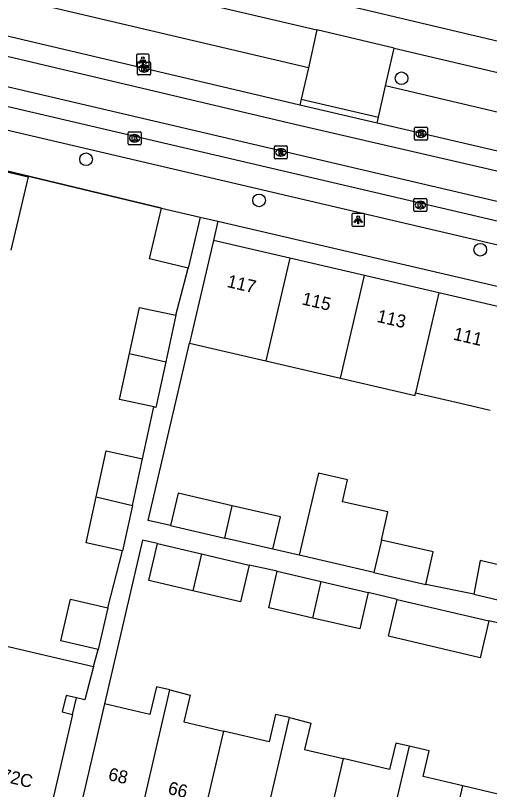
# Model space of a CAD drawing. Extents: x 163686 to 164493, y 382719 to 383870.
# Drawn here: x 163838.9 to 163875.6, y 383368 to 383427.9 of the extents above; entities that cross this region are included whole.
import ezdxf

# ---------------------------------------------------------------- set-up
doc = ezdxf.new("R2010")
doc.units = 0
for name, color, linetype in [('IMGEO_Boom', 7, 'Continuous'), ('IMGEO_Groenvoorziening', 7, 'Continuous'), ('IMGEO_Kolk', 7, 'Continuous'), ('IMGEO_Lichtpunt', 7, 'Continuous'), ('IMGEO_Muur', 7, 'Continuous'), ('IMGEO_Pand', 7, 'Continuous'), ('IMGEO_Pand_nummerreeks', 7, 'Continuous'), ('IMGEO_Rijbaan_lokaal_open', 7, 'Continuous'), ('IMGEO_Rioolput', 7, 'Continuous'), ('IMGEO_Voetpad_open', 7, 'Continuous')]:
    doc.layers.add(name, color=color, linetype=linetype)

msp = doc.modelspace()

# ---------------------------------------------------------------- linework, layer by layer
at = {"layer": 'IMGEO_Boom'}
for centre in [(163868.779, 383423.003), (163844.366, 383416.735), (163857.755, 383413.552), (163874.871, 383409.739)]:
    msp.add_circle(centre, 0.489, dxfattribs=at)
at = {"layer": 'IMGEO_Groenvoorziening'}
for points in [[(163861.569, 383423.819), (163837.373, 383429.512)], [(163890.603, 383416.989), (163867.54, 383422.415)]]:
    msp.add_lwpolyline(points, dxfattribs=at)
at = {"layer": 'IMGEO_Kolk'}
for p, q in [((163848.355, 383423.333), (163848.355, 383424.185)), ((163848.43, 383424.259), (163849.282, 383424.259)), ((163848.843, 383424.039), (163848.868, 383424.039)), ((163849.356, 383424.185), (163849.356, 383423.333)), ((163848.866, 383423.479), (163848.841, 383423.479)), ((163849.282, 383423.259), (163848.43, 383423.259)), ((163869.862, 383419.213), (163870.714, 383419.213)), ((163847.624, 383417.937), (163847.624, 383418.789)), ((163847.699, 383418.863), (163848.551, 383418.863)), ((163848.112, 383418.643), (163848.137, 383418.643)), ((163848.625, 383418.789), (163848.625, 383417.937)), ((163869.787, 383418.287), (163869.787, 383419.139)), ((163870.275, 383418.993), (163870.3, 383418.993)), ((163870.788, 383419.139), (163870.788, 383418.287)), ((163848.135, 383418.083), (163848.11, 383418.083)), ((163870.714, 383418.213), (163869.862, 383418.213)), ((163870.298, 383418.433), (163870.273, 383418.433)), ((163848.551, 383417.863), (163847.699, 383417.863)), ((163869.744, 383412.767), (163869.744, 383413.619)), ((163869.819, 383413.693), (163870.671, 383413.693)), ((163870.232, 383413.473), (163870.257, 383413.473)), ((163870.745, 383413.619), (163870.745, 383412.767)), ((163870.671, 383412.693), (163869.819, 383412.693)), ((163870.255, 383412.913), (163870.23, 383412.913))]:
    msp.add_line(p, q, dxfattribs=at)
for points in [[(163848.355, 383423.333), (163848.355, 383424.185)], [(163848.43, 383424.259), (163849.282, 383424.259)], [(163849.356, 383424.185), (163849.356, 383423.333)], [(163848.676, 383423.959), (163848.799, 383423.959), (163848.799, 383423.808), (163848.929, 383423.959), (163849.093, 383423.959), (163848.947, 383423.808), (163849.1, 383423.559), (163848.948, 383423.559), (163848.863, 383423.723), (163848.799, 383423.656), (163848.799, 383423.559), (163848.676, 383423.559), (163848.676, 383423.959)], [(163849.282, 383423.259), (163848.43, 383423.259)], [(163869.862, 383419.213), (163870.714, 383419.213)], [(163847.624, 383417.937), (163847.624, 383418.789)], [(163847.699, 383418.863), (163848.551, 383418.863)], [(163848.625, 383418.789), (163848.625, 383417.937)], [(163869.787, 383418.287), (163869.787, 383419.139)], [(163870.108, 383418.913), (163870.231, 383418.913), (163870.231, 383418.762), (163870.361, 383418.913), (163870.525, 383418.913), (163870.379, 383418.762), (163870.532, 383418.513), (163870.38, 383418.513), (163870.295, 383418.677), (163870.231, 383418.61), (163870.231, 383418.513), (163870.108, 383418.513), (163870.108, 383418.913)], [(163870.788, 383419.139), (163870.788, 383418.287)], [(163847.945, 383418.563), (163848.068, 383418.563), (163848.068, 383418.412), (163848.198, 383418.563), (163848.362, 383418.563), (163848.216, 383418.412), (163848.369, 383418.163), (163848.217, 383418.163), (163848.132, 383418.327), (163848.068, 383418.26), (163848.068, 383418.163), (163847.945, 383418.163), (163847.945, 383418.563)], [(163870.714, 383418.213), (163869.862, 383418.213)], [(163848.551, 383417.863), (163847.699, 383417.863)], [(163869.744, 383412.767), (163869.744, 383413.619)], [(163869.819, 383413.693), (163870.671, 383413.693)], [(163870.065, 383413.393), (163870.188, 383413.393), (163870.188, 383413.242), (163870.318, 383413.393), (163870.482, 383413.393), (163870.336, 383413.242), (163870.489, 383412.993), (163870.337, 383412.993), (163870.252, 383413.157), (163870.188, 383413.09), (163870.188, 383412.993), (163870.065, 383412.993), (163870.065, 383413.393)], [(163870.745, 383413.619), (163870.745, 383412.767)], [(163870.671, 383412.693), (163869.819, 383412.693)]]:
    msp.add_lwpolyline(points, dxfattribs=at)
for centre, start, end in [((163848.432, 383424.183), 91.55205, 178.44795), ((163848.432, 383424.183), 91.55205, 178.44795), ((163849.28, 383424.183), 1.55205, 88.44795), ((163849.28, 383424.183), 1.55205, 88.44795), ((163848.432, 383423.335), 181.55205, 268.44795), ((163848.432, 383423.335), 181.55205, 268.44795), ((163849.28, 383423.335), 271.55205, 358.44795), ((163849.28, 383423.335), 271.55205, 358.44795), ((163869.864, 383419.137), 91.55205, 178.44795), ((163869.864, 383419.137), 91.55205, 178.44795), ((163870.712, 383419.137), 1.55205, 88.44795), ((163870.712, 383419.137), 1.55205, 88.44795), ((163847.701, 383418.787), 91.55205, 178.44795), ((163847.701, 383418.787), 91.55205, 178.44795), ((163848.549, 383418.787), 1.55205, 88.44795), ((163848.549, 383418.787), 1.55205, 88.44795), ((163869.864, 383418.289), 181.55205, 268.44795), ((163869.864, 383418.289), 181.55205, 268.44795), ((163870.712, 383418.289), 271.55205, 358.44795), ((163870.712, 383418.289), 271.55205, 358.44795), ((163847.701, 383417.939), 181.55205, 268.44795), ((163847.701, 383417.939), 181.55205, 268.44795), ((163848.549, 383417.939), 271.55205, 358.44795), ((163848.549, 383417.939), 271.55205, 358.44795), ((163869.821, 383413.617), 91.55205, 178.44795), ((163869.821, 383413.617), 91.55205, 178.44795), ((163870.669, 383413.617), 1.55205, 88.44795), ((163870.669, 383413.617), 1.55205, 88.44795), ((163869.821, 383412.769), 181.55205, 268.44795), ((163869.821, 383412.769), 181.55205, 268.44795), ((163870.669, 383412.769), 271.55205, 358.44795), ((163870.669, 383412.769), 271.55205, 358.44795)]:
    msp.add_arc(centre, 0.0765, start, end, dxfattribs=at)
for centre, major_axis, ratio, start_param, end_param in [((163848.842, 383423.759), (-0.387, 0.002), 0.722429, 4.712389, 7.853982), ((163848.867, 383423.759), (-0.39, 0.002), 0.717154, 1.570796, 4.712389), ((163848.111, 383418.363), (-0.387, 0.002), 0.722429, 4.712389, 7.853982), ((163848.136, 383418.363), (-0.39, 0.002), 0.717154, 1.570796, 4.712389), ((163870.274, 383418.713), (-0.387, 0.002), 0.722429, 4.712389, 7.853982), ((163870.299, 383418.713), (-0.39, 0.002), 0.717154, 1.570796, 4.712389), ((163870.231, 383413.193), (-0.387, 0.002), 0.722429, 4.712389, 7.853982), ((163870.256, 383413.193), (-0.39, 0.002), 0.717154, 1.570796, 4.712389)]:
    msp.add_ellipse(centre, major_axis=major_axis, ratio=ratio, start_param=start_param, end_param=end_param, dxfattribs=at)
at = {"layer": 'IMGEO_Lichtpunt'}
for p, q in [((163848.262, 383424.771), (163848.262, 383423.964)), ((163848.262, 383424.771), (163848.262, 383423.964)), ((163849.164, 383424.866), (163848.356, 383424.866)), ((163849.164, 383424.866), (163848.356, 383424.866)), ((163849.258, 383423.964), (163849.258, 383424.771)), ((163849.258, 383423.964), (163849.258, 383424.771)), ((163848.356, 383423.87), (163849.164, 383423.87)), ((163848.356, 383423.87), (163849.164, 383423.87)), ((163864.924, 383412.457), (163864.924, 383411.65)), ((163864.924, 383412.457), (163864.924, 383411.65)), ((163865.826, 383412.552), (163865.018, 383412.552)), ((163865.826, 383412.552), (163865.018, 383412.552)), ((163865.92, 383411.65), (163865.92, 383412.457)), ((163865.92, 383411.65), (163865.92, 383412.457)), ((163865.018, 383411.556), (163865.826, 383411.556)), ((163865.018, 383411.556), (163865.826, 383411.556))]:
    msp.add_line(p, q, dxfattribs=at)
for points in [[(163848.636, 383424.435), (163848.675, 383424.407), (163848.487, 383424.145), (163848.449, 383424.172), (163848.636, 383424.435)], [(163848.738, 383424.387), (163848.785, 383424.387), (163848.785, 383424.065), (163848.738, 383424.065), (163848.738, 383424.387)], [(163848.848, 383424.407), (163848.886, 383424.434), (163849.073, 383424.172), (163849.034, 383424.144), (163848.848, 383424.407)], [(163865.298, 383412.121), (163865.337, 383412.093), (163865.149, 383411.831), (163865.111, 383411.858), (163865.298, 383412.121)], [(163865.4, 383412.073), (163865.447, 383412.073), (163865.447, 383411.751), (163865.4, 383411.751), (163865.4, 383412.073)], [(163865.51, 383412.093), (163865.548, 383412.12), (163865.735, 383411.858), (163865.696, 383411.83), (163865.51, 383412.093)]]:
    msp.add_lwpolyline(points, dxfattribs=at)
for centre in [(163848.761, 383424.569), (163865.423, 383412.255)]:
    msp.add_circle(centre, 0.0994, dxfattribs=at)
for centre, start, end in [((163848.356, 383424.771), 90, 180), ((163848.356, 383424.771), 90, 180), ((163849.164, 383424.771), 0, 90), ((163849.164, 383424.771), 0, 90), ((163848.356, 383423.964), 180, 270), ((163848.356, 383423.964), 180, 270), ((163849.164, 383423.964), 270, 0), ((163849.164, 383423.964), 270, 360), ((163865.018, 383412.457), 90, 180), ((163865.018, 383412.457), 90, 180), ((163865.826, 383412.457), 0, 90), ((163865.826, 383412.457), 0, 90), ((163865.018, 383411.65), 180, 270), ((163865.018, 383411.65), 180, 270), ((163865.826, 383411.65), 270, 0), ((163865.826, 383411.65), 270, 360)]:
    msp.add_arc(centre, 0.0946, start, end, dxfattribs=at)
at = {"layer": 'IMGEO_Muur'}
msp.add_lwpolyline([(163832.675, 383417.164), (163850.201, 383412.963)], dxfattribs=at)
at = {"layer": 'IMGEO_Pand'}
for points in [[(163831.226, 383411.426), (163832.55, 383417.097), (163839.879, 383415.386), (163838.555, 383409.716)], [(163852.278, 383408.324), (163849.282, 383409.023), (163850.201, 383412.963)], [(163850.201, 383412.963), (163853.197, 383412.264)], [(163853.197, 383412.264), (163852.278, 383408.324)], [(163854.218, 383410.461), (163853.088, 383405.602), (163852.37, 383402.515)], [(163860.136, 383409.085), (163854.218, 383410.461)], [(163860.136, 383409.085), (163858.287, 383401.139)], [(163865.905, 383407.744), (163860.136, 383409.085)], [(163864.056, 383399.797), (163865.905, 383407.744)], [(163871.674, 383406.403), (163865.905, 383407.744)], [(163871.674, 383406.403), (163869.873, 383398.666)], [(163877.443, 383405.061), (163871.674, 383406.403)], [(163847.737, 383401.717), (163848.512, 383405.276), (163851.324, 383404.664)], [(163851.324, 383404.664), (163850.54, 383401.063)], [(163852.37, 383402.515), (163858.287, 383401.139)], [(163849.609, 383397.58), (163846.961, 383398.157), (163847.737, 383401.717)], [(163847.737, 383401.717), (163850.54, 383401.063)], [(163850.54, 383401.063), (163849.773, 383397.544), (163849.609, 383397.58)], [(163858.287, 383401.139), (163864.056, 383399.797)], [(163864.056, 383399.797), (163869.824, 383398.456), (163869.873, 383398.666)], [(163869.873, 383398.666), (163873.353, 383397.858), (163875.643, 383397.326)], [(163845.144, 383390.609), (163845.92, 383394.171), (163848.732, 383393.559)], [(163847.947, 383389.955), (163848.732, 383393.559)], [(163867.222, 383387.275), (163867.724, 383389.465), (163864.202, 383390.241), (163864.595, 383391.93), (163862.347, 383392.454), (163861.947, 383390.735), (163860.867, 383386.099)], [(163847.181, 383386.439), (163844.369, 383387.052), (163845.144, 383390.609)], [(163845.144, 383390.609), (163847.947, 383389.955)], [(163855.68, 383389.934), (163851.489, 383390.899), (163850.911, 383388.392)], [(163847.947, 383389.955), (163847.181, 383386.439)], [(163855.096, 383387.428), (163855.68, 383389.934)], [(163858.829, 383386.568), (163859.406, 383389.076), (163855.68, 383389.934)], [(163850.911, 383388.392), (163855.096, 383387.428)], [(163852.641, 383383.348), (163849.222, 383384.146), (163849.888, 383387)], [(163849.888, 383387), (163853.306, 383386.202)], [(163858.829, 383386.568), (163855.096, 383387.428)], [(163867.222, 383387.275), (163866.639, 383384.769)], [(163870.649, 383383.845), (163871.227, 383386.353), (163867.222, 383387.275)], [(163853.306, 383386.202), (163852.641, 383383.348)], [(163853.306, 383386.202), (163856.995, 383385.341)], [(163866.639, 383384.769), (163860.867, 383386.099)], [(163878.799, 383384.756), (163874.868, 383385.69), (163874.373, 383383.094)], [(163856.995, 383385.341), (163856.328, 383382.487), (163852.641, 383383.348)], [(163861.916, 383381.245), (163858.51, 383382.04), (163859.167, 383384.857)], [(163859.167, 383384.857), (163862.573, 383384.062)], [(163866.639, 383384.769), (163870.649, 383383.845)], [(163861.916, 383381.245), (163862.573, 383384.062)], [(163862.573, 383384.062), (163866.209, 383383.213)], [(163845.297, 383378.815), (163842.409, 383379.489), (163843.162, 383382.714), (163846.05, 383382.04)], [(163866.209, 383383.213), (163865.551, 383380.396), (163861.916, 383381.245)], [(163875.537, 383381.033), (163874.87, 383378.176), (163867.773, 383379.833), (163868.44, 383382.69)], [(163868.44, 383382.69), (163875.537, 383381.033)], [(163874.373, 383383.094), (163878.201, 383382.185)], [(163846.05, 383382.04), (163845.297, 383378.815)], [(163836.623, 383375.303), (163837.541, 383379.232), (163844.951, 383377.502)], [(163844.951, 383377.502), (163844.27, 383374.924), (163843.625, 383375.074)], [(163850.853, 383375.687), (163849.806, 383375.932), (163849.304, 383373.78), (163845.801, 383374.598)], [(163848.49, 383365.56), (163850.853, 383375.687)], [(163850.853, 383375.687), (163852.427, 383375.286), (163851.943, 383373.213), (163854.992, 383372.501)], [(163843.625, 383375.074), (163842.822, 383375.262), (163842.522, 383373.977), (163843.325, 383373.79)], [(163845.801, 383374.598), (163845.076, 383371.492), (163843.939, 383366.622)], [(163843.325, 383373.79), (163842.459, 383370.08), (163841.322, 383365.21)], [(163860.116, 383373.536), (163859.036, 383373.788), (163858.542, 383371.673), (163854.992, 383372.501)], [(163857.749, 383363.398), (163860.116, 383373.536)], [(163860.116, 383373.536), (163860.306, 383373.492), (163861.752, 383373.114), (163861.273, 383371.063), (163864.258, 383370.366)], [(163854.992, 383372.501), (163853.12, 383364.479)], [(163869.363, 383371.328), (163868.327, 383371.57), (163867.85, 383369.527), (163864.258, 383370.366)], [(163869.363, 383371.328), (163867.009, 383361.237)], [(163873.53, 383368.256), (163870.442, 383368.977), (163870.907, 383370.968), (163869.363, 383371.328)], [(163864.258, 383370.366), (163862.38, 383362.317)], [(163878.631, 383369.196), (163877.584, 383369.44), (163877.112, 383367.419), (163873.53, 383368.256)], [(163871.64, 383360.155), (163873.53, 383368.256)]]:
    msp.add_lwpolyline(points, dxfattribs=at)
at = {"layer": 'IMGEO_Rijbaan_lokaal_open'}
for points in [[(163827.854, 383427.16), (163860.525, 383419.464), (163892.693, 383412.027)], [(163860.921, 383420.912), (163836.716, 383426.613)], [(163892.163, 383409.724), (163827.318, 383424.902)], [(163891.83, 383408.274), (163827.942, 383423.215)], [(163866.886, 383419.533), (163860.921, 383420.912)], [(163889.964, 383414.169), (163866.886, 383419.533)]]:
    msp.add_lwpolyline(points, dxfattribs=at)
at = {"layer": 'IMGEO_Rioolput'}
for p, q in [((163858.938, 383416.84), (163858.938, 383417.692)), ((163859.013, 383417.766), (163859.865, 383417.766)), ((163859.426, 383417.546), (163859.451, 383417.546)), ((163859.939, 383417.692), (163859.939, 383416.84)), ((163859.449, 383416.986), (163859.424, 383416.986)), ((163859.865, 383416.766), (163859.013, 383416.766))]:
    msp.add_line(p, q, dxfattribs=at)
for points in [[(163858.938, 383416.84), (163858.938, 383417.692)], [(163859.013, 383417.766), (163859.865, 383417.766)], [(163859.527, 383417.464), (163859.275, 383417.466), (163859.275, 383417.066)], [(163859.939, 383417.692), (163859.939, 383416.84)], [(163859.275, 383417.066), (163859.399, 383417.066), (163859.399, 383417.228), (163859.41, 383417.228)], [(163859.453, 383417.385), (163859.399, 383417.385), (163859.399, 383417.304)], [(163859.399, 383417.304), (163859.451, 383417.304)], [(163859.457, 383417.199), (163859.528, 383417.066), (163859.668, 383417.066), (163859.603, 383417.192)], [(163859.865, 383416.766), (163859.013, 383416.766)]]:
    msp.add_lwpolyline(points, dxfattribs=at)
for centre, radius, start, end in [((163859.015, 383417.69), 0.0765, 91.55205, 178.44795), ((163859.015, 383417.69), 0.0765, 91.55205, 178.44795), ((163859.526, 383417.354), 0.109, 350.36119, 89.41601), ((163859.863, 383417.69), 0.0765, 1.55205, 88.44795), ((163859.863, 383417.69), 0.0765, 1.55205, 88.44795), ((163859.015, 383416.842), 0.0765, 181.55205, 268.44795), ((163859.015, 383416.842), 0.0765, 181.55205, 268.44795), ((163859.409, 383417.175), 0.0533, 26.02933, 88.69889), ((163859.435, 383417.493), 0.19, 274.7715, 282.96867), ((163859.459, 383417.289), 0.0964, 77.00612, 93.18647), ((163859.473, 383417.346), 0.0378, 276.66336, 79.67722), ((163859.524, 383417.354), 0.112, 277.58423, 350.98172), ((163859.508, 383417.139), 0.108, 29.51342, 73.79051), ((163859.863, 383416.842), 0.0765, 271.55205, 358.44795), ((163859.863, 383416.842), 0.0765, 271.55205, 358.44795)]:
    msp.add_arc(centre, radius, start, end, dxfattribs=at)
for centre, major_axis, ratio, start_param, end_param in [((163859.425, 383417.266), (-0.387, 0.002), 0.722429, 4.712389, 7.853982), ((163859.45, 383417.266), (-0.39, 0.002), 0.717154, 1.570796, 4.712389)]:
    msp.add_ellipse(centre, major_axis=major_axis, ratio=ratio, start_param=start_param, end_param=end_param, dxfattribs=at)
at = {"layer": 'IMGEO_Voetpad_open'}
for points in [[(163831.477, 383436.455), (163837.936, 383434.797), (163843.936, 383433.408), (163866.249, 383428.241), (163868.851, 383427.627), (163899.759, 383420.325)], [(163838.037, 383432.437), (163862.222, 383426.748)], [(163862.222, 383426.748), (163861.569, 383423.819)], [(163868.201, 383425.328), (163862.222, 383426.748)], [(163867.54, 383422.415), (163868.201, 383425.328)], [(163868.201, 383425.328), (163891.265, 383419.907)], [(163861.569, 383423.819), (163861.025, 383421.375)], [(163866.991, 383419.994), (163867.54, 383422.415)], [(163861.025, 383421.375), (163860.921, 383420.912)], [(163861.025, 383421.375), (163866.991, 383419.994)], [(163903.102, 383403.799), (163830.362, 383420.809)], [(163866.886, 383419.533), (163866.991, 383419.994)], [(163850.201, 383412.963), (163832.675, 383417.164), (163831.753, 383417.404)], [(163853.197, 383412.264), (163854.563, 383411.946)], [(163854.563, 383411.946), (163854.218, 383410.461)], [(163854.563, 383411.946), (163906.774, 383399.807)], [(163851.324, 383404.664), (163852.278, 383408.324)], [(163850.911, 383388.392), (163849.168, 383388.794), (163852.37, 383402.515)], [(163848.732, 383393.559), (163849.609, 383397.58)], [(163849.888, 383387), (163848.721, 383387.273), (163845.801, 383374.598)], [(163846.05, 383382.04), (163847.181, 383386.439)], [(163860.867, 383386.099), (163858.829, 383386.568)], [(163859.167, 383384.857), (163856.995, 383385.341)], [(163874.373, 383383.094), (163870.649, 383383.845)], [(163868.44, 383382.69), (163866.209, 383383.213)], [(163877.798, 383380.513), (163875.537, 383381.033)], [(163844.951, 383377.502), (163845.297, 383378.815)], [(163843.325, 383373.79), (163843.625, 383375.074)]]:
    msp.add_lwpolyline(points, dxfattribs=at)

# ---------------------------------------------------------------- texts
at = {"layer": 'IMGEO_Pand_nummerreeks'}
for s, rotation, p in [('117', 346.91174, (163855.212, 383406.863)), ('115', 346.91364, (163861.013, 383405.514)), ('113', 346.91364, (163866.815, 383404.165)), ('111', 346.91364, (163872.727, 383402.79)), ('70-72C', 346.79332, (163835.828, 383369.087)), ('68', 346.86016, (163846.02, 383368.724)), ('66', 346.86016, (163850.639, 383367.646))]:
    msp.add_text(s, height=1, rotation=rotation, dxfattribs=at).set_placement(p)

doc.saveas('drawing.dxf')
